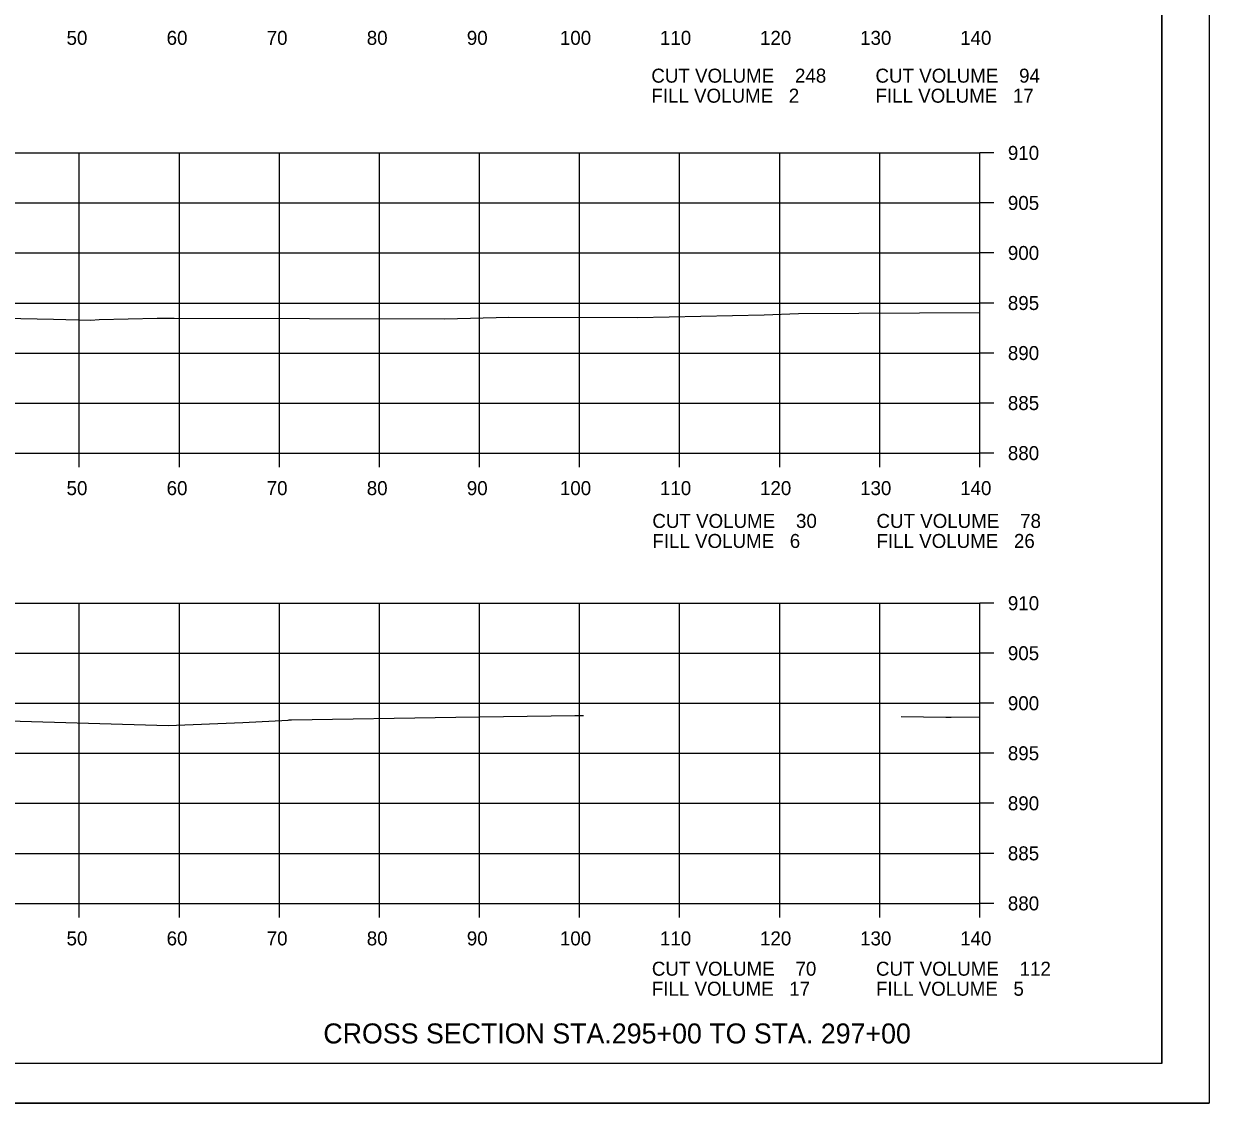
# Model space of a CAD drawing. Extents: x 1486524 to 1499135, y 326561 to 337924.
# Drawn here: x 1489027.3 to 1489145.8, y 333419.3 to 333527.2 of the extents above; entities that cross this region are included whole.
import ezdxf

# ---------------------------------------------------------------- set-up
doc = ezdxf.new("R2010")
doc.units = 0
for name, color, linetype in [('E_Const Align', 7, 'Continuous'), ('E_Const Align Station', 7, 'Continuous'), ('E_Ownership Information', 7, 'Continuous'), ('E_Property Line', 7, 'Continuous'), ('E_Proposed ROW Fig Annot', 7, 'Continuous'), ('E_Quarter Calls', 7, 'Continuous'), ('E_Tract Number', 7, 'Continuous')]:
    doc.layers.add(name, color=color, linetype=linetype)

msp = doc.modelspace()

# ---------------------------------------------------------------- linework, layer by layer
at = {"layer": 'E_Const Align'}
for p, q in [((1489122.89, 333484.3), (1489122.89, 333514.3)), ((1489124.29, 333514.3), (1489122.89, 333514.3)), ((1489124.29, 333509.3), (1489122.89, 333509.3)), ((1489124.29, 333504.3), (1489122.89, 333504.3)), ((1489124.29, 333499.3), (1489122.89, 333499.3)), ((1489124.29, 333494.3), (1489122.89, 333494.3)), ((1489124.29, 333489.3), (1489122.89, 333489.3)), ((1488842.89, 333484.3), (1489122.89, 333484.3)), ((1489032.89, 333482.9), (1489032.89, 333484.3)), ((1489042.89, 333482.9), (1489042.89, 333484.3)), ((1489052.89, 333482.9), (1489052.89, 333484.3)), ((1489062.89, 333482.9), (1489062.89, 333484.3)), ((1489072.89, 333482.9), (1489072.89, 333484.3)), ((1489082.89, 333482.9), (1489082.89, 333484.3)), ((1489092.89, 333482.9), (1489092.89, 333484.3)), ((1489102.89, 333482.9), (1489102.89, 333484.3)), ((1489112.89, 333482.9), (1489112.89, 333484.3)), ((1489122.89, 333482.9), (1489122.89, 333484.3)), ((1489124.29, 333484.3), (1489122.89, 333484.3)), ((1489122.89, 333439.3), (1489122.89, 333469.3)), ((1489124.29, 333469.3), (1489122.89, 333469.3)), ((1489124.29, 333464.3), (1489122.89, 333464.3)), ((1489124.29, 333459.3), (1489122.89, 333459.3)), ((1489124.29, 333454.3), (1489122.89, 333454.3)), ((1489124.29, 333449.3), (1489122.89, 333449.3)), ((1489124.29, 333444.3), (1489122.89, 333444.3)), ((1488842.89, 333439.3), (1489122.89, 333439.3)), ((1489032.89, 333437.9), (1489032.89, 333439.3)), ((1489042.89, 333437.9), (1489042.89, 333439.3)), ((1489052.89, 333437.9), (1489052.89, 333439.3)), ((1489062.89, 333437.9), (1489062.89, 333439.3)), ((1489072.89, 333437.9), (1489072.89, 333439.3)), ((1489082.89, 333437.9), (1489082.89, 333439.3)), ((1489092.89, 333437.9), (1489092.89, 333439.3)), ((1489102.89, 333437.9), (1489102.89, 333439.3)), ((1489112.89, 333437.9), (1489112.89, 333439.3)), ((1489122.89, 333437.9), (1489122.89, 333439.3)), ((1489124.29, 333439.3), (1489122.89, 333439.3))]:
    msp.add_line(p, q, dxfattribs=at)
at = {"layer": 'E_Ownership Information'}
for p, q in [((1488842.89, 333514.3), (1489122.89, 333514.3)), ((1489032.89, 333484.3), (1489032.89, 333514.3)), ((1489042.89, 333484.3), (1489042.89, 333514.3)), ((1489052.89, 333484.3), (1489052.89, 333514.3)), ((1489062.89, 333484.3), (1489062.89, 333514.3)), ((1489072.89, 333484.3), (1489072.89, 333514.3)), ((1489082.89, 333484.3), (1489082.89, 333514.3)), ((1489092.89, 333484.3), (1489092.89, 333514.3)), ((1489102.89, 333484.3), (1489102.89, 333514.3)), ((1489112.89, 333484.3), (1489112.89, 333514.3)), ((1489122.89, 333484.3), (1489122.89, 333514.3)), ((1488842.89, 333509.3), (1489122.89, 333509.3)), ((1488842.89, 333504.3), (1489122.89, 333504.3)), ((1488842.89, 333499.3), (1489122.89, 333499.3)), ((1488842.89, 333494.3), (1489122.89, 333494.3)), ((1488842.89, 333489.3), (1489122.89, 333489.3)), ((1488842.89, 333484.3), (1489122.89, 333484.3)), ((1488842.89, 333469.3), (1489122.89, 333469.3)), ((1488842.89, 333469.3), (1489122.89, 333469.3)), ((1489032.89, 333439.3), (1489032.89, 333469.3)), ((1489032.89, 333439.3), (1489032.89, 333469.3)), ((1489042.89, 333439.3), (1489042.89, 333469.3)), ((1489042.89, 333439.3), (1489042.89, 333469.3)), ((1489052.89, 333439.3), (1489052.89, 333469.3)), ((1489052.89, 333439.3), (1489052.89, 333469.3)), ((1489062.89, 333439.3), (1489062.89, 333469.3)), ((1489062.89, 333439.3), (1489062.89, 333469.3)), ((1489072.89, 333439.3), (1489072.89, 333469.3)), ((1489072.89, 333439.3), (1489072.89, 333469.3)), ((1489082.89, 333439.3), (1489082.89, 333469.3)), ((1489082.89, 333439.3), (1489082.89, 333469.3)), ((1489092.89, 333439.3), (1489092.89, 333469.3)), ((1489092.89, 333439.3), (1489092.89, 333469.3)), ((1489102.89, 333439.3), (1489102.89, 333469.3)), ((1489102.89, 333439.3), (1489102.89, 333469.3)), ((1489112.89, 333439.3), (1489112.89, 333469.3)), ((1489112.89, 333439.3), (1489112.89, 333469.3)), ((1489122.89, 333439.3), (1489122.89, 333469.3)), ((1489122.89, 333439.3), (1489122.89, 333469.3)), ((1488842.89, 333464.3), (1489122.89, 333464.3)), ((1488842.89, 333464.3), (1489122.89, 333464.3)), ((1488842.89, 333459.3), (1489122.89, 333459.3)), ((1488842.89, 333459.3), (1489122.89, 333459.3)), ((1488842.89, 333454.3), (1489122.89, 333454.3)), ((1488842.89, 333454.3), (1489122.89, 333454.3)), ((1488842.89, 333449.3), (1489122.89, 333449.3)), ((1488842.89, 333449.3), (1489122.89, 333449.3)), ((1488842.89, 333444.3), (1489122.89, 333444.3)), ((1488842.89, 333444.3), (1489122.89, 333444.3)), ((1488842.89, 333439.3), (1489122.89, 333439.3)), ((1488842.89, 333439.3), (1489122.89, 333439.3))]:
    msp.add_line(p, q, dxfattribs=at)
at = {"layer": 'E_Property Line'}
for q in [(1489141.07, 333628.76), (1488824.89, 333423.3)]:
    msp.add_line((1489141.07, 333423.3), q, dxfattribs=at)
at = {"layer": 'E_Quarter Calls'}
msp.add_line((1488812.48, 333419.32), (1489145.82, 333419.32), dxfattribs=at)
for points in [[(1488812.48, 333632.66), (1489145.82, 333632.66), (1489145.82, 333419.32), (1488812.48, 333419.32)], [(1489058.81, 333628.76), (1489058.81, 333618.88), (1489094.54, 333618.88), (1489094.54, 333615.96), (1489117.74, 333615.96), (1489117.74, 333591.63), (1489141.07, 333591.63), (1489141.07, 333423.3), (1488824.89, 333423.3), (1488824.89, 333628.76)]]:
    msp.add_lwpolyline(points, close=True, dxfattribs=at)
at = {"layer": 'E_Tract Number'}
for points in [[(1489020.51, 333497.88), (1489030.3, 333497.69), (1489034.05, 333497.59), (1489034.88, 333497.64), (1489040.66, 333497.8), (1489042.36, 333497.78), (1489069.43, 333497.71), (1489075.82, 333497.88), (1489088.67, 333497.86), (1489101.35, 333498.11), (1489104.76, 333498.26), (1489122.89, 333498.36)], [(1489025.86, 333457.53), (1489041.78, 333457.08), (1489049.25, 333457.38), (1489053.78, 333457.62), (1489053.86, 333457.63), (1489053.88, 333457.63), (1489054.11, 333457.63), (1489070.52, 333457.92), (1489082.4, 333458.06), (1489083.27, 333458.07)], [(1489115.03, 333457.96), (1489119.49, 333457.92), (1489120.01, 333457.92), (1489122.89, 333457.95)]]:
    msp.add_lwpolyline(points, dxfattribs=at)

# ---------------------------------------------------------------- texts
at = {"layer": 'E_Const Align Station'}
for s, p in [('50', (1489031.62, 333525.1)), ('60', (1489041.62, 333525.1)), ('70', (1489051.62, 333525.1)), ('80', (1489061.62, 333525.1)), ('90', (1489071.62, 333525.1)), ('100', (1489080.92, 333525.1)), ('110', (1489090.92, 333525.1)), ('120', (1489100.92, 333525.1)), ('130', (1489110.92, 333525.1)), ('140', (1489120.92, 333525.1)), ('CUT VOLUME    248', (1489090.06, 333521.32)), ('CUT VOLUME    94', (1489112.46, 333521.32)), ('FILL VOLUME   2', (1489090.06, 333519.32)), ('FILL VOLUME   17', (1489112.46, 333519.32)), ('910', (1489125.69, 333513.6)), ('905', (1489125.69, 333508.6)), ('900', (1489125.69, 333503.6)), ('895', (1489125.69, 333498.6)), ('890', (1489125.69, 333493.6)), ('885', (1489125.69, 333488.6)), ('880', (1489125.69, 333483.6)), ('50', (1489031.62, 333480.1)), ('60', (1489041.62, 333480.1)), ('70', (1489051.62, 333480.1)), ('80', (1489061.62, 333480.1)), ('90', (1489071.62, 333480.1)), ('100', (1489080.92, 333480.1)), ('110', (1489090.92, 333480.1)), ('120', (1489100.92, 333480.1)), ('130', (1489110.92, 333480.1)), ('140', (1489120.92, 333480.1)), ('CUT VOLUME    30', (1489090.16, 333476.82)), ('CUT VOLUME    78', (1489112.56, 333476.82)), ('FILL VOLUME   6', (1489090.16, 333474.82)), ('FILL VOLUME   26', (1489112.56, 333474.82)), ('910', (1489125.69, 333468.6)), ('905', (1489125.69, 333463.6)), ('900', (1489125.69, 333458.6)), ('895', (1489125.69, 333453.6)), ('890', (1489125.69, 333448.6)), ('885', (1489125.69, 333443.6)), ('880', (1489125.69, 333438.6)), ('50', (1489031.62, 333435.1)), ('60', (1489041.62, 333435.1)), ('70', (1489051.62, 333435.1)), ('80', (1489061.62, 333435.1)), ('90', (1489071.62, 333435.1)), ('100', (1489080.92, 333435.1)), ('110', (1489090.92, 333435.1)), ('120', (1489100.92, 333435.1)), ('130', (1489110.92, 333435.1)), ('140', (1489120.92, 333435.1)), ('CUT VOLUME    70', (1489090.11, 333432.07)), ('CUT VOLUME    112', (1489112.51, 333432.07)), ('FILL VOLUME   17', (1489090.11, 333430.07)), ('FILL VOLUME   5', (1489112.51, 333430.07))]:
    msp.add_text(s, height=1.4, dxfattribs=at).set_placement(p)
at = {"layer": 'E_Proposed ROW Fig Annot'}
msp.add_text('CROSS SECTION STA.295+00 TO STA. 297+00', height=2, dxfattribs=at).set_placement((1489057.28, 333425.3))

doc.saveas('drawing.dxf')
